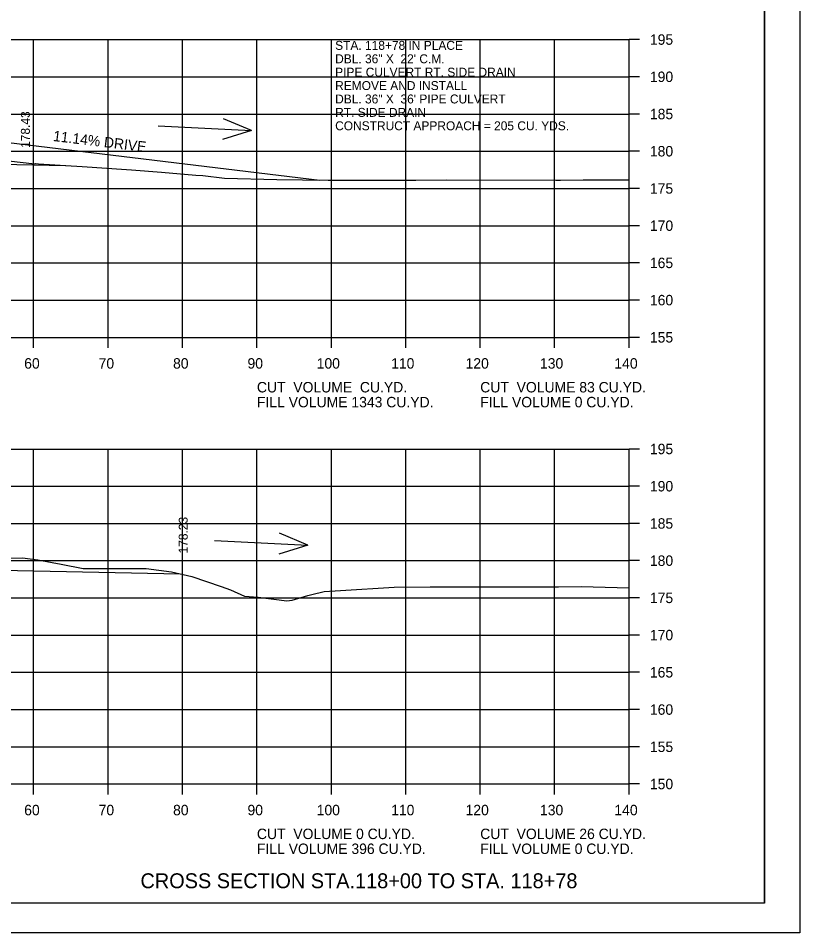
# Model space of a CAD drawing. Extents: x 915787 to 919910, y 133456 to 136717.
# Drawn here: x 916471.9 to 916576.9, y 135589.4 to 135712.2 of the extents above; entities that cross this region are included whole.
import ezdxf

# ---------------------------------------------------------------- set-up
doc = ezdxf.new("R2010")
doc.units = 0
for name, color, linetype in [('R_Axis', 7, 'Continuous'), ('R_Axis Annot', 7, 'Continuous'), ('R_Border', 7, 'Continuous'), ('R_Border Notes', 7, 'Continuous'), ('R_Draft', 7, 'Continuous'), ('R_Drive', 7, 'Continuous'), ('R_Exist Surface', 7, 'Continuous'), ('R_Fin Surface', 7, 'Continuous'), ('R_Grid', 7, 'Continuous'), ('R_No Plot', 7, 'Continuous'), ('R_Water Annot', 7, 'Continuous'), ('R_Xsect Elev', 7, 'Continuous')]:
    doc.layers.add(name, color=color, linetype=linetype)

msp = doc.modelspace()

# ---------------------------------------------------------------- linework, layer by layer
at = {"layer": 'R_Axis'}
for p, q in [((916553.98, 135669.39), (916553.98, 135709.39)), ((916555.38, 135709.39), (916553.98, 135709.39)), ((916555.38, 135704.39), (916553.98, 135704.39)), ((916555.38, 135699.39), (916553.98, 135699.39)), ((916555.38, 135694.39), (916553.98, 135694.39)), ((916555.38, 135689.39), (916553.98, 135689.39)), ((916555.38, 135684.39), (916553.98, 135684.39)), ((916555.38, 135679.39), (916553.98, 135679.39)), ((916555.38, 135674.39), (916553.98, 135674.39)), ((916273.98, 135669.39), (916553.98, 135669.39)), ((916473.98, 135667.99), (916473.98, 135669.39)), ((916483.98, 135667.99), (916483.98, 135669.39)), ((916493.98, 135667.99), (916493.98, 135669.39)), ((916503.98, 135667.99), (916503.98, 135669.39)), ((916513.98, 135667.99), (916513.98, 135669.39)), ((916523.98, 135667.99), (916523.98, 135669.39)), ((916533.98, 135667.99), (916533.98, 135669.39)), ((916543.98, 135667.99), (916543.98, 135669.39)), ((916553.98, 135667.99), (916553.98, 135669.39)), ((916555.38, 135669.39), (916553.98, 135669.39)), ((916553.98, 135609.39), (916553.98, 135654.39)), ((916555.38, 135654.39), (916553.98, 135654.39)), ((916555.38, 135649.39), (916553.98, 135649.39)), ((916555.38, 135644.39), (916553.98, 135644.39)), ((916555.38, 135639.39), (916553.98, 135639.39)), ((916555.38, 135634.39), (916553.98, 135634.39)), ((916555.38, 135629.39), (916553.98, 135629.39)), ((916555.38, 135624.39), (916553.98, 135624.39)), ((916555.38, 135619.39), (916553.98, 135619.39)), ((916555.38, 135614.39), (916553.98, 135614.39)), ((916273.98, 135609.39), (916553.98, 135609.39)), ((916473.98, 135607.99), (916473.98, 135609.39)), ((916483.98, 135607.99), (916483.98, 135609.39)), ((916493.98, 135607.99), (916493.98, 135609.39)), ((916503.98, 135607.99), (916503.98, 135609.39)), ((916513.98, 135607.99), (916513.98, 135609.39)), ((916523.98, 135607.99), (916523.98, 135609.39)), ((916533.98, 135607.99), (916533.98, 135609.39)), ((916543.98, 135607.99), (916543.98, 135609.39)), ((916553.98, 135607.99), (916553.98, 135609.39)), ((916555.38, 135609.39), (916553.98, 135609.39))]:
    msp.add_line(p, q, dxfattribs=at)
at = {"layer": 'R_Border'}
for q in [(916572.16, 135798.85), (916255.98, 135593.39)]:
    msp.add_line((916572.16, 135593.39), q, dxfattribs=at)
at = {"layer": 'R_Drive'}
msp.add_line((916459.93, 135696.82), (916512.45, 135690.52), dxfattribs=at)
at = {"layer": 'R_Exist Surface'}
for points in [[(916468.97, 135693.27), (916474.14, 135692.7), (916474.29, 135692.72), (916474.62, 135692.7), (916480.51, 135692.33), (916486.46, 135691.93), (916487.13, 135691.88), (916491.15, 135691.57), (916495.77, 135691.18), (916496.72, 135691.12), (916499.64, 135690.75), (916506.67, 135690.61), (916513.53, 135690.51), (916525.31, 135690.51), (916529.45, 135690.53), (916544.13, 135690.52), (916544.75, 135690.52), (916547.81, 135690.53), (916553.98, 135690.56)], [(916468.49, 135639.67), (916472.46, 135639.77), (916474.52, 135639.51), (916474.53, 135639.51), (916474.56, 135639.51), (916477.66, 135638.91), (916480.63, 135638.34), (916480.79, 135638.32), (916489.1, 135638.35), (916492.51, 135637.89), (916495.23, 135637.26), (916499.19, 135635.9), (916500.41, 135635.45), (916502.32, 135634.61), (916504.16, 135634.48), (916508, 135634.01), (916508.71, 135634.1), (916510.84, 135634.72), (916511.35, 135634.86), (916513, 135635.26), (916515.23, 135635.39), (916522.42, 135635.85), (916527.25, 135635.88), (916539.16, 135635.88), (916544.5, 135635.89), (916547.53, 135635.93), (916553.98, 135635.75)]]:
    msp.add_lwpolyline(points, dxfattribs=at)
at = {"layer": 'R_Fin Surface'}
for points in [[(916362.11, 135685.66), (916371.66, 135688.84), (916382.97, 135692.61), (916384.11, 135692.9), (916385.11, 135693.15), (916388.56, 135694.01), (916391.47, 135694.74), (916397.66, 135695.08), (916402.97, 135695.35), (916408.89, 135695.68), (916413.97, 135695.94), (916419.89, 135696.27), (916424.97, 135696.53), (916428.21, 135696.71), (916430.97, 135696.85), (916434.32, 135696.01), (916438.32, 135695.01), (916441.38, 135694.25), (916444.97, 135693.35), (916445.27, 135693.25), (916445.62, 135693.13), (916478.28, 135692.48)], [(916356.48, 135629.63), (916382.97, 135638.47), (916386.57, 135639.37), (916391.47, 135640.61), (916402.97, 135641.07), (916413.97, 135641.37), (916424.97, 135641.67), (916430.97, 135641.83), (916447.75, 135638.54), (916493.67, 135637.62)]]:
    msp.add_lwpolyline(points, dxfattribs=at)
at = {"layer": 'R_Grid'}
for p, q in [((916273.98, 135709.39), (916553.98, 135709.39)), ((916473.98, 135669.39), (916473.98, 135709.39)), ((916483.98, 135669.39), (916483.98, 135709.39)), ((916493.98, 135669.39), (916493.98, 135709.39)), ((916503.98, 135669.39), (916503.98, 135709.39)), ((916513.98, 135669.39), (916513.98, 135709.39)), ((916523.98, 135669.39), (916523.98, 135709.39)), ((916533.98, 135669.39), (916533.98, 135709.39)), ((916543.98, 135669.39), (916543.98, 135709.39)), ((916553.98, 135669.39), (916553.98, 135709.39)), ((916273.98, 135704.39), (916553.98, 135704.39)), ((916273.98, 135699.39), (916553.98, 135699.39)), ((916273.98, 135694.39), (916553.98, 135694.39)), ((916273.98, 135689.39), (916553.98, 135689.39)), ((916273.98, 135684.39), (916553.98, 135684.39)), ((916273.98, 135679.39), (916553.98, 135679.39)), ((916273.98, 135674.39), (916553.98, 135674.39)), ((916273.98, 135669.39), (916553.98, 135669.39)), ((916273.98, 135654.39), (916553.98, 135654.39)), ((916473.98, 135609.39), (916473.98, 135654.39)), ((916483.98, 135609.39), (916483.98, 135654.39)), ((916493.98, 135609.39), (916493.98, 135654.39)), ((916503.98, 135609.39), (916503.98, 135654.39)), ((916513.98, 135609.39), (916513.98, 135654.39)), ((916523.98, 135609.39), (916523.98, 135654.39)), ((916533.98, 135609.39), (916533.98, 135654.39)), ((916543.98, 135609.39), (916543.98, 135654.39)), ((916553.98, 135609.39), (916553.98, 135654.39)), ((916273.98, 135649.39), (916553.98, 135649.39)), ((916273.98, 135644.39), (916553.98, 135644.39)), ((916273.98, 135639.39), (916553.98, 135639.39)), ((916273.98, 135634.39), (916553.98, 135634.39)), ((916273.98, 135629.39), (916553.98, 135629.39)), ((916273.98, 135624.39), (916553.98, 135624.39)), ((916273.98, 135619.39), (916553.98, 135619.39)), ((916273.98, 135614.39), (916553.98, 135614.39)), ((916273.98, 135609.39), (916553.98, 135609.39))]:
    msp.add_line(p, q, dxfattribs=at)
at = {"layer": 'R_No Plot'}
msp.add_line((916243.57, 135589.42), (916576.91, 135589.42), dxfattribs=at)
for points in [[(916243.57, 135802.75), (916576.91, 135802.75), (916576.91, 135589.41), (916243.57, 135589.41)], [(916489.9, 135798.85), (916489.9, 135788.97), (916525.63, 135788.97), (916525.63, 135786.05), (916548.83, 135786.05), (916548.83, 135762.84), (916572.16, 135762.84), (916572.16, 135593.39), (916255.98, 135593.39), (916255.98, 135798.85)]]:
    msp.add_lwpolyline(points, close=True, dxfattribs=at)
at = {"layer": 'R_Water Annot'}
for p, q in [((916503.25, 135697.18), (916499.48, 135698.76)), ((916490.7, 135697.78), (916503.25, 135697.18)), ((916503.25, 135697.18), (916499.34, 135695.97)), ((916510.81, 135641.49), (916507.03, 135643.07)), ((916498.26, 135642.09), (916510.81, 135641.49)), ((916510.81, 135641.49), (916506.9, 135640.27))]:
    msp.add_line(p, q, dxfattribs=at)

# ---------------------------------------------------------------- texts
at = {"layer": 'R_Axis Annot'}
for s, p in [('195', (916556.78, 135708.69)), ('190', (916556.78, 135703.69)), ('185', (916556.78, 135698.69)), ('180', (916556.78, 135693.69)), ('175', (916556.78, 135688.69)), ('170', (916556.78, 135683.69)), ('165', (916556.78, 135678.69)), ('160', (916556.78, 135673.69)), ('155', (916556.78, 135668.69)), ('60', (916472.71, 135665.19)), ('70', (916482.71, 135665.19)), ('80', (916492.71, 135665.19)), ('90', (916502.71, 135665.19)), ('100', (916512.01, 135665.19)), ('110', (916522.01, 135665.19)), ('120', (916532.01, 135665.19)), ('130', (916542.01, 135665.19)), ('140', (916552.01, 135665.19)), ('195', (916556.78, 135653.69)), ('190', (916556.78, 135648.69)), ('185', (916556.78, 135643.69)), ('180', (916556.78, 135638.69)), ('175', (916556.78, 135633.69)), ('170', (916556.78, 135628.69)), ('165', (916556.78, 135623.69)), ('160', (916556.78, 135618.69)), ('155', (916556.78, 135613.69)), ('150', (916556.78, 135608.69)), ('60', (916472.71, 135605.19)), ('70', (916482.71, 135605.19)), ('80', (916492.71, 135605.19)), ('90', (916502.71, 135605.19)), ('100', (916512.01, 135605.19)), ('110', (916522.01, 135605.19)), ('120', (916532.01, 135605.19)), ('130', (916542.01, 135605.19)), ('140', (916552.01, 135605.19))]:
    msp.add_text(s, height=1.4, dxfattribs=at).set_placement(p)
at = {"layer": 'R_Border Notes'}
for s, p in [('CUT  VOLUME  CU.YD.', (916503.98, 135661.99)), ('CUT  VOLUME 83 CU.YD.', (916533.98, 135661.99)), ('FILL VOLUME 1343 CU.YD.', (916503.98, 135659.99)), ('FILL VOLUME 0 CU.YD.', (916533.98, 135659.99)), ('CUT  VOLUME 0 CU.YD.', (916503.98, 135601.99)), ('CUT  VOLUME 26 CU.YD.', (916533.98, 135601.99)), ('FILL VOLUME 396 CU.YD.', (916503.98, 135599.99)), ('FILL VOLUME 0 CU.YD.', (916533.98, 135599.99))]:
    msp.add_text(s, height=1.4, dxfattribs=at).set_placement(p)
at = {"layer": 'R_Draft'}
msp.add_text('CROSS SECTION STA.118+00 TO STA. 118+78', height=2, dxfattribs=at).set_placement((916488.33, 135595.39))
at = {"layer": 'R_Drive'}
msp.add_text('11.14% DRIVE', height=1.4, rotation=353.1572, dxfattribs=at).set_placement((916476.54, 135695.77))
at = {"layer": 'R_Water Annot'}
for s, p in [('STA. 118+78 IN PLACE', (916514.49, 135708.01)), ('DBL. 36" X  22\' C.M.   ', (916514.49, 135706.21)), ('PIPE CULVERT RT. SIDE DRAIN', (916514.49, 135704.41)), ('REMOVE AND INSTALL', (916514.49, 135702.61)), ('DBL. 36" X  36\' PIPE CULVERT', (916514.49, 135700.81)), ('RT. SIDE DRAIN', (916514.49, 135699.01)), ('CONSTRUCT APPROACH = 205 CU. YDS.', (916514.49, 135697.21))]:
    msp.add_text(s, height=1.2, dxfattribs=at).set_placement(p)
at = {"layer": 'R_Xsect Elev'}
for s, p in [('178.43', (916473.47, 135694.84)), ('178.23', (916494.67, 135640.36))]:
    msp.add_text(s, height=1.2, rotation=90, dxfattribs=at).set_placement(p)

doc.saveas('drawing.dxf')
